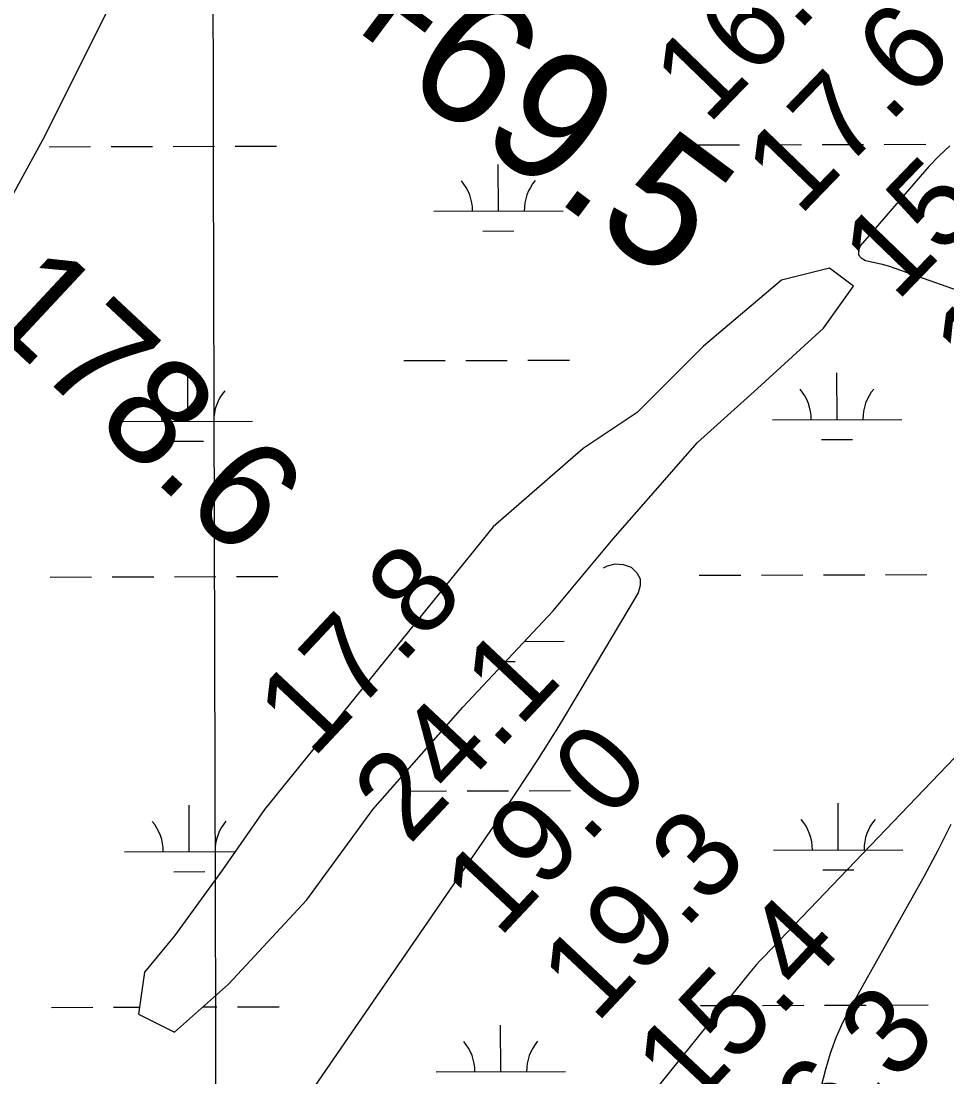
# Model space of a CAD drawing. Extents: x 3361039 to 3398939, y 576572 to 602007.
# Drawn here: x 3375519 to 3376235, y 592663 to 593479 of the extents above; entities that cross this region are included whole.
import ezdxf

# ---------------------------------------------------------------- set-up
doc = ezdxf.new("R2010")
doc.units = 0
for name, color, linetype in [('V-GRID-MAJR', 7, 'Continuous'), ('V-RIVR-RANG', 7, 'Continuous'), ('V-RIVR-RANG-IDEN', 7, 'Continuous'), ('V-SITE-VEGE', 7, 'Continuous'), ('V-SURV-IDEN', 7, 'Continuous'), ('V-TOPO-MINR', 7, 'Continuous'), ('V-WETL-SWMP', 7, 'Continuous')]:
    doc.layers.add(name, color=color, linetype=linetype)

msp = doc.modelspace()

# ---------------------------------------------------------------- linework, layer by layer
at = {"layer": 'V-GRID-MAJR'}
msp.add_spline([(3375697.58, 581986.07), (3375681.72, 588044.11), (3375665.85, 594105.25), (3375649.98, 600166.4), (3375649.97, 600169.46)], degree=3, dxfattribs=at)
at = {"layer": 'V-SITE-VEGE'}
msp.add_lwpolyline([(3375486.31, 593297.9), (3375537.43, 593390.93), (3375583.91, 593483.95)], dxfattribs=at)
msp.add_lwpolyline([(3375883.73, 593088.59), (3375707.12, 592869.98), (3375674.58, 592823.46), (3375637.4, 592772.3), (3375614.16, 592744.39), (3375609.52, 592711.83), (3375637.4, 592697.88), (3375679.23, 592735.09), (3375739.65, 592800.21), (3375790.78, 592869.98), (3375860.49, 592949.05), (3375930.21, 593023.47), (3375976.69, 593079.29), (3376041.76, 593153.71), (3376088.23, 593195.57), (3376139.36, 593242.08), (3376162.6, 593274.64), (3376144, 593288.59), (3376106.82, 593279.29), (3376046.4, 593228.13), (3375995.28, 593176.96), (3375953.45, 593149.06)], close=True, dxfattribs=at)
at = {"layer": 'V-TOPO-MINR'}
for points in [[(3376236.97, 593383.06), (3376228.61, 593375.29), (3376220.72, 593366.98), (3376167.67, 593305.64), (3376166.38, 593302), (3376166.4, 593298.84)], [(3376166.4, 593298.84), (3376168.4, 593296.38), (3376171.7, 593294.4), (3376177.66, 593293.23), (3376183.57, 593291.85), (3376189.4, 593290.17), (3376195.17, 593288.29), (3376269.02, 593262.09)], [(3375969.29, 593056.79), (3375972.25, 593058.36), (3375978.22, 593059.98), (3375984.37, 593059.36), (3375990.65, 593057.25), (3375994.9, 593053.06), (3375997.48, 593048.42), (3375997.55, 593043.12), (3375995.94, 593037.37), (3375950.22, 592960.47), (3375934.29, 592934.28), (3375918.02, 592908.31), (3375901.24, 592882.67), (3375884.12, 592857.24), (3375263.19, 591954.8)], [(3376240.62, 592910.01), (3376093.03, 592756.19), (3376090.28, 592753.25), (3376087.58, 592750.26), (3376084.96, 592747.21), (3376082.39, 592744.11), (3375809.77, 592406.07), (3375728.9, 592305.18), (3375648.44, 592203.97), (3375568.6, 592102.27), (3375489.16, 592000.25)], [(3376133.89, 592641.48), (3376141.07, 592669.25), (3376144.77, 592681.57), (3376149.09, 592693.65), (3376154.34, 592705.35), (3376160.2, 592716.8), (3376217.42, 592818.62), (3376228.07, 592838.57), (3376238.11, 592858.8)]]:
    msp.add_lwpolyline(points, dxfattribs=at)
at = {"layer": 'V-WETL-SWMP'}
for p, q in [((3376042.33, 593383.78), (3376074.33, 593383.86)), ((3376090.33, 593383.91), (3376122.33, 593384)), ((3376138.33, 593384.04), (3376170.33, 593384.13)), ((3376186.33, 593384.17), (3376218.33, 593384.26)), ((3375540.42, 593382.39), (3375572.42, 593382.48)), ((3375588.42, 593382.52), (3375620.42, 593382.61)), ((3375636.42, 593382.65), (3375668.42, 593382.74)), ((3375684.42, 593382.79), (3375716.42, 593382.87)), ((3375887.88, 593332.61), (3375887.78, 593368.61)), ((3375837.88, 593332.47), (3375937.88, 593332.74)), ((3375875.92, 593317.14), (3375899.92, 593317.21)), ((3375814.79, 593216.97), (3375846.79, 593217.06)), ((3375862.79, 593217.1), (3375894.79, 593217.19)), ((3375910.79, 593217.24), (3375942.79, 593217.33)), ((3375647.85, 593170.08), (3375647.75, 593206.08)), ((3376149.76, 593171.47), (3376149.66, 593207.47)), ((3376099.76, 593171.33), (3376199.76, 593171.61)), ((3375597.85, 593169.94), (3375697.85, 593170.22)), ((3376137.8, 593156), (3376161.8, 593156.07)), ((3375635.9, 593154.62), (3375659.9, 593154.68)), ((3375541.34, 593049.71), (3375573.34, 593049.8)), ((3375589.34, 593049.85), (3375621.34, 593049.94)), ((3375637.34, 593049.98), (3375669.34, 593050.07)), ((3375685.34, 593050.11), (3375717.34, 593050.2)), ((3376043.25, 593051.1), (3376075.25, 593051.19)), ((3376091.25, 593051.23), (3376123.25, 593051.32)), ((3376139.25, 593051.37), (3376171.25, 593051.46)), ((3376187.25, 593051.5), (3376219.25, 593051.59)), ((3375908.21, 592999.99), (3375938.8, 593000.07)), ((3375893.72, 592984.52), (3375900.84, 592984.53)), ((3375815.71, 592884.3), (3375847.71, 592884.39)), ((3375863.71, 592884.43), (3375895.71, 592884.52)), ((3375911.71, 592884.56), (3375943.71, 592884.65)), ((3375648.77, 592837.41), (3375648.67, 592873.41)), ((3376150.68, 592838.79), (3376150.58, 592874.79)), ((3375598.77, 592837.27), (3375684.41, 592837.51)), ((3376100.68, 592838.66), (3376200.68, 592838.93)), ((3375636.81, 592821.94), (3375660.81, 592822.01)), ((3376138.72, 592823.33), (3376162.72, 592823.4)), ((3375542.26, 592717.04), (3375574.26, 592717.13)), ((3375590.26, 592717.17), (3375610.29, 592717.23)), ((3375659.3, 592717.36), (3375670.26, 592717.39)), ((3375686.26, 592717.44), (3375718.26, 592717.53)), ((3376044.17, 592718.43), (3376076.17, 592718.52)), ((3376092.17, 592718.56), (3376124.17, 592718.65)), ((3376140.17, 592718.69), (3376172.17, 592718.78)), ((3376188.17, 592718.83), (3376220.17, 592718.91)), ((3375889.71, 592667.26), (3375889.62, 592703.26)), ((3375839.72, 592667.12), (3375939.71, 592667.4))]:
    msp.add_line(p, q, dxfattribs=at)
msp.add_lwpolyline([(3375486.31, 593297.9), (3375537.43, 593390.93), (3375583.91, 593483.95), (3375644.33, 593595.59), (3375690.81, 593646.75), (3375714.05, 593660.7), (3375718.69, 593670.01), (3375704.75, 593707.22), (3375723.34, 593730.47), (3375727.99, 593753.73), (3375727.99, 593772.34), (3375723.34, 593790.94), (3375723.02, 593790.94), (3375734.6, 593800.68)], dxfattribs=at)
msp.add_lwpolyline([(3375637.4, 592772.3), (3375614.16, 592744.39), (3375609.52, 592711.83), (3375637.4, 592697.88), (3375679.23, 592735.09), (3375739.65, 592800.21), (3375790.78, 592869.98), (3375860.49, 592949.05), (3375930.21, 593023.47), (3375976.69, 593079.29), (3376041.75, 593153.71), (3376088.23, 593195.57), (3376139.36, 593242.08), (3376162.6, 593274.64), (3376144, 593288.59), (3376106.82, 593279.29), (3376046.4, 593228.13), (3375995.28, 593176.96), (3375953.45, 593149.06), (3375883.73, 593088.59), (3375707.12, 592869.98), (3375674.58, 592823.46)], close=True, dxfattribs=at)
for centre, start, end in [((3375832.63, 593332.93), 359.38648, 40.93014), ((3375943.12, 593333.23), 139.38648, 180.93014), ((3375592.61, 593170.4), 359.38648, 40.93014), ((3375703.09, 593170.71), 139.38648, 180.93014), ((3376094.51, 593171.79), 359.38648, 40.93014), ((3376205, 593172.09), 139.38648, 180.93014), ((3375944.04, 593000.56), 179.92485, 180.93014), ((3376095.43, 592839.12), 359.38648, 40.93014), ((3376205.92, 592839.42), 139.38648, 180.93014), ((3375593.53, 592837.73), 359.38648, 40.93014), ((3375704.01, 592838.03), 139.38648, 180.93014), ((3375834.47, 592667.58), 359.38648, 40.93014), ((3375944.96, 592667.89), 139.38648, 180.93014)]:
    msp.add_arc(centre, 35.25, start, end, dxfattribs=at)

# ---------------------------------------------------------------- texts
at = {"layer": 'V-RIVR-RANG'}
for s, rotation, p in [('16.4', 45.96833, (3376049.87, 593398.46)), ('17.6', 45.96833, (3376120.66, 593327.81)), ('15.1', 45.96833, (3376195.67, 593261.52)), ('15.4', 45.96833, (3376266.09, 593190.49)), ('17.8', 46.82833, (3375744.18, 592908.36)), ('24.1', 46.82833, (3375818.9, 592841.85)), ('19.0', 46.82833, (3375888.38, 592769.76)), ('19.3', 46.82833, (3375963.46, 592703.63)), ('15.4', 46.82833, (3376036.56, 592635.39)), ('16.3', 46.82833, (3376109.65, 592567.14))]:
    msp.add_text(s, height=67, rotation=rotation, dxfattribs=at).set_placement(p)
at = {"layer": 'V-RIVR-RANG-IDEN'}
msp.add_text('R-178.6', height=83, rotation=316.96558, dxfattribs=at).set_placement((3375398.74, 593332.32))
at = {"layer": 'V-SURV-IDEN'}
msp.add_text('6006+69.5', height=100, rotation=323.28452, dxfattribs=at).set_placement((3375509.53, 593656.5))

doc.saveas('drawing.dxf')
